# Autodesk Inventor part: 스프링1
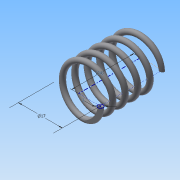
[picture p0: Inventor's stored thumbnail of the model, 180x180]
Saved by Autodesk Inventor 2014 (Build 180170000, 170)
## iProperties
Created: 2016-01
Part Number: 스프링1
Material: 강철, 탄소
Document SubType Name: Modeling
Designer: Administrator
Density: 7.87 g/cm^3
Appearance: 반연마
Mass: 6.46669 g
Surface Area: 16.7182 cm^2
Volume: 0.821689 cm^3
Author: Administrator
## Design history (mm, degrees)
sketch "스케치1"
  geometry: L1 (0, 0)-(8.5, 0); L2 (8.5, 0)-(8.5, 20.5); L3 (8.5, 20.5)-(0, 20.5); L4 (0, 20.5)-(0, 0); C1 r 1 at (8.5, 0)
  constraints: 8 end point, 2 parallel, 1 centre point, 1 coincident, 1 horizontal, 1 perpendicular
  dimensions: "d0" = 17 diameter of L2 L4; "d1" = 20.5 distance of L3.end L1.start (derived); "d2" = 2 diameter of C1
feature "코일1" sketch "스케치1" pitch "d3" = 10; turns "d5" = 5; dims "d4" = 20.5 (= d1), "d6" = 0, angle "d7" = 90 deg, angle "d8" = 90 deg, "d9" = 0, "d10" = 0
node "작업 평면1"
sketch "스케치2"
  geometry: L1 (-9.5, 0)-(-7.5, 0) reference; 1 further point
  constraints: 1 horizontal alignment
extrude "돌출1" cut sketch "스케치2" stored distance "d12" = 10; taper "d13" = 0 deg
node "작업 평면2"
sketch "스케치3"
  geometry: L1 (-7.5, 0)-(-9.5, 0) reference; 1 further point
  constraints: 1 horizontal alignment
extrude "돌출2" cut sketch "스케치3" stored distance "d15" = 10; taper "d16" = 0 deg
node "솔리드1"
node "절단 모서리 투영1"
node "절단 모서리 투영2"
other parameters: "d11" = 0, "d14" = 20.5 (= d1)
